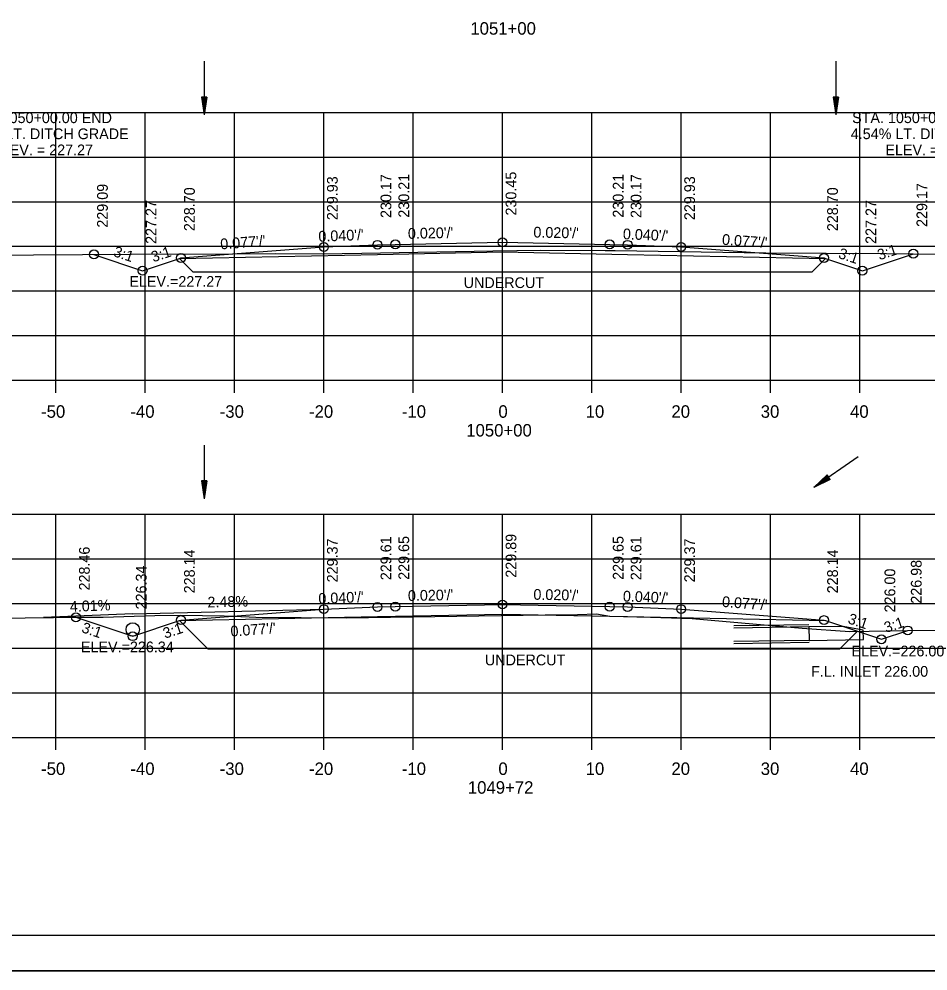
# Model space of a CAD drawing. Extents: x 1386544 to 1388153, y 379785 to 390999.
# Drawn here: x 1387305.6 to 1387407.3, y 387585.5 to 387692.1 of the extents above; entities that cross this region are included whole.
import ezdxf

# ---------------------------------------------------------------- set-up
doc = ezdxf.new("R2010")
doc.units = 0
for name, color, linetype in [('R_Alt Surface', 7, 'Continuous'), ('R_Axis', 7, 'Continuous'), ('R_Axis Annot', 7, 'Continuous'), ('R_Border', 7, 'Continuous'), ('R_Dimension', 7, 'Continuous'), ('R_Drive', 7, 'Continuous'), ('R_Exist Surface', 7, 'Continuous'), ('R_Fin Surface', 7, 'Continuous'), ('R_Grid', 7, 'Continuous'), ('R_No Plot', 7, 'Continuous'), ('R_Water', 7, 'Continuous'), ('R_Water Annot', 7, 'Continuous'), ('R_Xsect Elev', 7, 'Continuous'), ('R_Xsect Slope', 7, 'Continuous')]:
    doc.layers.add(name, color=color, linetype=linetype)

msp = doc.modelspace()

# ---------------------------------------------------------------- linework, layer by layer
at = {"layer": 'R_Alt Surface'}
for points in [[(1387323.51, 387665.33), (1387345.68, 387665.77), (1387359.68, 387666.05), (1387373.68, 387665.77), (1387395.85, 387665.33)], [(1387323.51, 387624.77), (1387345.68, 387625.21), (1387359.68, 387625.49), (1387373.68, 387625.21), (1387395.85, 387624.77)]]:
    msp.add_lwpolyline(points, dxfattribs=at)
at = {"layer": 'R_Axis'}
for p, q in [((1387209.68, 387651.68), (1387509.68, 387651.68)), ((1387309.68, 387650.28), (1387309.68, 387651.68)), ((1387319.68, 387650.28), (1387319.68, 387651.68)), ((1387329.68, 387650.28), (1387329.68, 387651.68)), ((1387339.68, 387650.28), (1387339.68, 387651.68)), ((1387349.68, 387650.28), (1387349.68, 387651.68)), ((1387359.68, 387650.28), (1387359.68, 387651.68)), ((1387369.68, 387650.28), (1387369.68, 387651.68)), ((1387379.68, 387650.28), (1387379.68, 387651.68)), ((1387389.68, 387650.28), (1387389.68, 387651.68)), ((1387399.68, 387650.28), (1387399.68, 387651.68)), ((1387209.68, 387611.68), (1387509.68, 387611.68)), ((1387309.68, 387610.28), (1387309.68, 387611.68)), ((1387319.68, 387610.28), (1387319.68, 387611.68)), ((1387329.68, 387610.28), (1387329.68, 387611.68)), ((1387339.68, 387610.28), (1387339.68, 387611.68)), ((1387349.68, 387610.28), (1387349.68, 387611.68)), ((1387359.68, 387610.28), (1387359.68, 387611.68)), ((1387369.68, 387610.28), (1387369.68, 387611.68)), ((1387379.68, 387610.28), (1387379.68, 387611.68)), ((1387389.68, 387610.28), (1387389.68, 387611.68)), ((1387399.68, 387610.28), (1387399.68, 387611.68))]:
    msp.add_line(p, q, dxfattribs=at)
at = {"layer": 'R_Border'}
msp.add_line((1387517.86, 387589.51), (1387201.68, 387589.51), dxfattribs=at)
at = {"layer": 'R_Dimension'}
for p, q in [((1387323.51, 387665.33), (1387325.02, 387663.81)), ((1387395.85, 387665.33), (1387394.33, 387663.81)), ((1387323.51, 387624.77), (1387326.72, 387621.56)), ((1387399.43, 387623.57), (1387397.41, 387621.56))]:
    msp.add_line(p, q, dxfattribs=at)
for points in [[(1387325.02, 387663.81), (1387394.33, 387663.81)], [(1387397.41, 387621.56), (1387326.72, 387621.56)]]:
    msp.add_lwpolyline(points, dxfattribs=at)
at = {"layer": 'R_Drive'}
for q in [(1387308.29, 387625.12), (1387339.68, 387626.05)]:
    msp.add_line((1387318.28, 387625.52), q, dxfattribs=at)
at = {"layer": 'R_Exist Surface'}
for points in [[(1387301.7, 387665.7), (1387318.11, 387665.79), (1387329.46, 387665.83), (1387334.22, 387665.86), (1387339.51, 387665.83), (1387343.92, 387665.9), (1387358.61, 387666.19), (1387363.96, 387666.26), (1387371.16, 387666.21), (1387372.28, 387666.21), (1387389.15, 387665.95), (1387402.66, 387665.89), (1387414.56, 387665.74)], [(1387292.2, 387624.84), (1387308.57, 387625.13), (1387309.4, 387625.13), (1387310.87, 387625.14), (1387311.88, 387625.14), (1387314.98, 387625.16), (1387320.76, 387625.34), (1387323.66, 387625.37), (1387328.51, 387625.31), (1387331.33, 387625.18), (1387332.06, 387625.16), (1387342.21, 387625.08), (1387364.47, 387625.41), (1387368.07, 387625.45), (1387370.2, 387625.52), (1387371.71, 387625.26), (1387376.25, 387625.15), (1387380.91, 387625), (1387393.24, 387623.93), (1387398.58, 387623.56), (1387405.02, 387623.66), (1387408.74, 387623.7)]]:
    msp.add_lwpolyline(points, dxfattribs=at)
at = {"layer": 'R_Fin Surface'}
for points in [[(1387313.94, 387665.77), (1387319.38, 387663.95), (1387323.51, 387665.33), (1387323.68, 387665.38), (1387339.68, 387666.61), (1387345.68, 387666.85), (1387347.68, 387666.89), (1387359.68, 387667.13), (1387371.68, 387666.89), (1387373.68, 387666.85), (1387379.68, 387666.61), (1387395.68, 387665.38), (1387395.85, 387665.33), (1387399.97, 387663.95), (1387405.68, 387665.85)], [(1387311.92, 387625.14), (1387318.28, 387623.02), (1387323.51, 387624.77), (1387323.68, 387624.82), (1387339.68, 387626.05), (1387345.68, 387626.29), (1387347.68, 387626.33), (1387359.68, 387626.57), (1387371.68, 387626.33), (1387373.68, 387626.29), (1387379.68, 387626.05), (1387395.68, 387624.82), (1387395.85, 387624.77), (1387402.1, 387622.68), (1387405.05, 387623.66)]]:
    msp.add_lwpolyline(points, dxfattribs=at)
at = {"layer": 'R_Grid'}
for p, q in [((1387209.68, 387681.68), (1387509.68, 387681.68)), ((1387309.68, 387651.68), (1387309.68, 387681.68)), ((1387319.68, 387651.68), (1387319.68, 387681.68)), ((1387329.68, 387651.68), (1387329.68, 387681.68)), ((1387339.68, 387651.68), (1387339.68, 387681.68)), ((1387349.68, 387651.68), (1387349.68, 387681.68)), ((1387359.68, 387651.68), (1387359.68, 387681.68)), ((1387369.68, 387651.68), (1387369.68, 387681.68)), ((1387379.68, 387651.68), (1387379.68, 387681.68)), ((1387389.68, 387651.68), (1387389.68, 387681.68)), ((1387399.68, 387651.68), (1387399.68, 387681.68)), ((1387209.68, 387676.68), (1387509.68, 387676.68)), ((1387209.68, 387671.68), (1387509.68, 387671.68)), ((1387209.68, 387666.68), (1387509.68, 387666.68)), ((1387209.68, 387661.68), (1387509.68, 387661.68)), ((1387209.68, 387656.68), (1387509.68, 387656.68)), ((1387209.68, 387651.68), (1387509.68, 387651.68)), ((1387209.68, 387636.68), (1387509.68, 387636.68)), ((1387309.68, 387611.68), (1387309.68, 387636.68)), ((1387319.68, 387611.68), (1387319.68, 387636.68)), ((1387329.68, 387611.68), (1387329.68, 387636.68)), ((1387339.68, 387611.68), (1387339.68, 387636.68)), ((1387349.68, 387611.68), (1387349.68, 387636.68)), ((1387359.68, 387611.68), (1387359.68, 387636.68)), ((1387369.68, 387611.68), (1387369.68, 387636.68)), ((1387379.68, 387611.68), (1387379.68, 387636.68)), ((1387389.68, 387611.68), (1387389.68, 387636.68)), ((1387399.68, 387611.68), (1387399.68, 387636.68)), ((1387209.68, 387631.68), (1387509.68, 387631.68)), ((1387209.68, 387626.68), (1387509.68, 387626.68)), ((1387209.68, 387621.68), (1387509.68, 387621.68)), ((1387209.68, 387616.68), (1387509.68, 387616.68)), ((1387209.68, 387611.68), (1387509.68, 387611.68))]:
    msp.add_line(p, q, dxfattribs=at)
at = {"layer": 'R_No Plot'}
for p, q in [((1387393.97, 387624.3), (1387385.59, 387624.17)), ((1387394, 387622.3), (1387385.59, 387622.17)), ((1387189.28, 387585.54), (1387522.61, 387585.54))]:
    msp.add_line(p, q, dxfattribs=at)
for points in [[(1387189.27, 387798.87), (1387522.61, 387798.87), (1387522.61, 387585.53), (1387189.27, 387585.53)], [(1387435.6, 387794.97), (1387455.22, 387794.97), (1387455.22, 387785.09), (1387471.33, 387785.09), (1387494.53, 387785.09), (1387494.53, 387760.76), (1387517.86, 387760.76), (1387517.86, 387589.51), (1387201.68, 387589.51), (1387201.68, 387794.97)]]:
    msp.add_lwpolyline(points, close=True, dxfattribs=at)
for centre in [(1387339.68, 387666.61), (1387345.68, 387666.85), (1387347.68, 387666.89), (1387359.68, 387667.13), (1387371.68, 387666.89), (1387373.68, 387666.85), (1387379.68, 387666.61), (1387313.94, 387665.77), (1387323.68, 387665.38), (1387395.68, 387665.38), (1387405.68, 387665.85), (1387319.38, 387663.95), (1387399.97, 387663.95), (1387339.68, 387626.05), (1387345.68, 387626.29), (1387347.68, 387626.33), (1387359.68, 387626.57), (1387371.68, 387626.33), (1387373.68, 387626.29), (1387379.68, 387626.05), (1387311.92, 387625.14), (1387323.68, 387624.82), (1387395.68, 387624.82), (1387405.05, 387623.66), (1387318.28, 387623.02), (1387402.1, 387622.68)]:
    msp.add_circle(centre, 0.5, dxfattribs=at)
at = {"layer": 'R_Water'}
for p, q in [((1387326.28, 387687.4), (1387326.28, 387681.4)), ((1387397.01, 387687.4), (1387397.01, 387681.4)), ((1387325.98, 387683.4), (1387326.28, 387681.4)), ((1387326.58, 387683.4), (1387325.98, 387683.4)), ((1387325.98, 387683.4), (1387326.28, 387681.4)), ((1387326.58, 387683.4), (1387325.98, 387683.4)), ((1387326.03, 387683.4), (1387326.28, 387681.73)), ((1387326.03, 387683.4), (1387326.28, 387681.73)), ((1387326.08, 387683.4), (1387326.28, 387682.08)), ((1387326.08, 387683.4), (1387326.28, 387682.08)), ((1387326.13, 387683.4), (1387326.28, 387682.41)), ((1387326.13, 387683.4), (1387326.28, 387682.41)), ((1387326.18, 387683.4), (1387326.28, 387682.75)), ((1387326.18, 387683.4), (1387326.28, 387682.75)), ((1387326.23, 387683.4), (1387326.28, 387683.08)), ((1387326.23, 387683.4), (1387326.28, 387683.08)), ((1387326.58, 387683.4), (1387326.28, 387681.4)), ((1387326.38, 387683.4), (1387326.28, 387682.75)), ((1387326.48, 387683.4), (1387326.28, 387682.08)), ((1387326.53, 387683.4), (1387326.28, 387681.73)), ((1387326.43, 387683.4), (1387326.28, 387682.41)), ((1387326.33, 387683.4), (1387326.28, 387683.08)), ((1387326.58, 387683.4), (1387326.28, 387681.4)), ((1387326.38, 387683.4), (1387326.28, 387682.75)), ((1387326.48, 387683.4), (1387326.28, 387682.08)), ((1387326.53, 387683.4), (1387326.28, 387681.73)), ((1387326.43, 387683.4), (1387326.28, 387682.41)), ((1387326.33, 387683.4), (1387326.28, 387683.08)), ((1387396.71, 387683.4), (1387397.01, 387681.4)), ((1387397.31, 387683.4), (1387396.71, 387683.4)), ((1387396.71, 387683.4), (1387397.01, 387681.4)), ((1387397.31, 387683.4), (1387396.71, 387683.4)), ((1387396.76, 387683.4), (1387397.01, 387681.73)), ((1387396.76, 387683.4), (1387397.01, 387681.73)), ((1387396.81, 387683.4), (1387397.01, 387682.08)), ((1387396.81, 387683.4), (1387397.01, 387682.08)), ((1387396.86, 387683.4), (1387397.01, 387682.41)), ((1387396.86, 387683.4), (1387397.01, 387682.41)), ((1387396.91, 387683.4), (1387397.01, 387682.75)), ((1387396.91, 387683.4), (1387397.01, 387682.75)), ((1387396.96, 387683.4), (1387397.01, 387683.08)), ((1387396.96, 387683.4), (1387397.01, 387683.08)), ((1387397.31, 387683.4), (1387397.01, 387681.4)), ((1387397.11, 387683.4), (1387397.01, 387682.75)), ((1387397.21, 387683.4), (1387397.01, 387682.08)), ((1387397.26, 387683.4), (1387397.01, 387681.73)), ((1387397.16, 387683.4), (1387397.01, 387682.41)), ((1387397.06, 387683.4), (1387397.01, 387683.08)), ((1387397.31, 387683.4), (1387397.01, 387681.4)), ((1387397.11, 387683.4), (1387397.01, 387682.75)), ((1387397.21, 387683.4), (1387397.01, 387682.08)), ((1387397.26, 387683.4), (1387397.01, 387681.73)), ((1387397.16, 387683.4), (1387397.01, 387682.41)), ((1387397.06, 387683.4), (1387397.01, 387683.08)), ((1387326.28, 387644.4), (1387326.28, 387638.4)), ((1387399.48, 387643.11), (1387394.55, 387639.69)), ((1387325.98, 387640.4), (1387326.28, 387638.4)), ((1387326.58, 387640.4), (1387325.98, 387640.4)), ((1387325.98, 387640.4), (1387326.28, 387638.4)), ((1387326.58, 387640.4), (1387325.98, 387640.4)), ((1387326.03, 387640.4), (1387326.28, 387638.73)), ((1387326.03, 387640.4), (1387326.28, 387638.73)), ((1387326.08, 387640.4), (1387326.28, 387639.08)), ((1387326.08, 387640.4), (1387326.28, 387639.08)), ((1387326.13, 387640.4), (1387326.28, 387639.41)), ((1387326.13, 387640.4), (1387326.28, 387639.41)), ((1387326.18, 387640.4), (1387326.28, 387639.75)), ((1387326.18, 387640.4), (1387326.28, 387639.75)), ((1387326.23, 387640.4), (1387326.28, 387640.08)), ((1387326.23, 387640.4), (1387326.28, 387640.08)), ((1387326.58, 387640.4), (1387326.28, 387638.4)), ((1387326.38, 387640.4), (1387326.28, 387639.75)), ((1387326.48, 387640.4), (1387326.28, 387639.08)), ((1387326.53, 387640.4), (1387326.28, 387638.73)), ((1387326.43, 387640.4), (1387326.28, 387639.41)), ((1387326.33, 387640.4), (1387326.28, 387640.08)), ((1387326.58, 387640.4), (1387326.28, 387638.4)), ((1387326.38, 387640.4), (1387326.28, 387639.75)), ((1387326.48, 387640.4), (1387326.28, 387639.08)), ((1387326.53, 387640.4), (1387326.28, 387638.73)), ((1387326.43, 387640.4), (1387326.28, 387639.41)), ((1387326.33, 387640.4), (1387326.28, 387640.08)), ((1387396.02, 387641.08), (1387394.55, 387639.69)), ((1387396.02, 387641.08), (1387394.55, 387639.69)), ((1387396.36, 387640.58), (1387394.55, 387639.69)), ((1387396.36, 387640.58), (1387394.55, 387639.69)), ((1387396.05, 387641.04), (1387394.82, 387639.88)), ((1387396.05, 387641.04), (1387394.82, 387639.88)), ((1387396.33, 387640.63), (1387394.82, 387639.88)), ((1387396.33, 387640.63), (1387394.82, 387639.88)), ((1387396.08, 387640.99), (1387395.1, 387640.08)), ((1387396.08, 387640.99), (1387395.1, 387640.08)), ((1387396.3, 387640.67), (1387395.1, 387640.08)), ((1387396.3, 387640.67), (1387395.1, 387640.08)), ((1387396.1, 387640.95), (1387395.38, 387640.27)), ((1387396.1, 387640.95), (1387395.38, 387640.27)), ((1387396.27, 387640.71), (1387395.38, 387640.27)), ((1387396.27, 387640.71), (1387395.38, 387640.27)), ((1387396.13, 387640.91), (1387395.65, 387640.46)), ((1387396.13, 387640.91), (1387395.65, 387640.46)), ((1387396.24, 387640.75), (1387395.65, 387640.46)), ((1387396.24, 387640.75), (1387395.65, 387640.46)), ((1387396.16, 387640.87), (1387395.93, 387640.65)), ((1387396.16, 387640.87), (1387395.93, 387640.65)), ((1387396.22, 387640.79), (1387395.93, 387640.65)), ((1387396.22, 387640.79), (1387395.93, 387640.65)), ((1387396.36, 387640.58), (1387396.02, 387641.08)), ((1387396.36, 387640.58), (1387396.02, 387641.08)), ((1387393.98, 387624.05), (1387385.59, 387623.92)), ((1387394, 387622.55), (1387385.59, 387622.42))]:
    msp.add_line(p, q, dxfattribs=at)
msp.add_lwpolyline([(1387393.98, 387624.05), (1387394, 387622.55), (1387400.08, 387622.65), (1387400.07, 387623.69), (1387397.81, 387624.11)], close=True, dxfattribs=at)
msp.add_circle((1387318.28, 387623.77), 0.75, dxfattribs=at)

# ---------------------------------------------------------------- texts
at = {"layer": 'R_Axis Annot'}
for s, p in [('1051+00', (1387356.08, 387690.38)), ('-50', (1387308.02, 387647.48)), ('-40', (1387318.02, 387647.48)), ('-30', (1387328.02, 387647.48)), ('-20', (1387338.02, 387647.48)), ('-10', (1387348.41, 387647.48)), ('0', (1387359.22, 387647.48)), ('10', (1387368.99, 387647.48)), ('20', (1387378.59, 387647.48)), ('30', (1387388.59, 387647.48)), ('40', (1387398.59, 387647.48)), ('1050+00', (1387355.62, 387645.38)), ('-50', (1387308.02, 387607.48)), ('-40', (1387318.02, 387607.48)), ('-30', (1387328.02, 387607.48)), ('-20', (1387338.02, 387607.48)), ('-10', (1387348.41, 387607.48)), ('0', (1387359.22, 387607.48)), ('10', (1387368.99, 387607.48)), ('20', (1387378.59, 387607.48)), ('30', (1387388.59, 387607.48)), ('40', (1387398.59, 387607.48)), ('1049+72', (1387355.8, 387605.38))]:
    msp.add_text(s, height=1.4, dxfattribs=at).set_placement(p)
at = {"layer": 'R_Dimension'}
for p in [(1387355.33, 387662.01), (1387357.71, 387619.76)]:
    msp.add_text('UNDERCUT', height=1.2, dxfattribs=at).set_placement(p)
at = {"layer": 'R_Water Annot'}
msp.add_text('F.L. INLET 226.00', height=1.2, dxfattribs=at).set_placement((1387394.22, 387618.48))
at = {"layer": 'R_Xsect Elev'}
for s, p in [('STA. 1050+00.00 END ', (1387299.59, 387680.48)), ('STA. 1050+00.00 BEGIN ', (1387398.82, 387680.48)), ('3.31% LT. DITCH GRADE', (1387299.01, 387678.68)), ('4.54% LT. DITCH GRADE', (1387398.67, 387678.68)), ('ELEV. = 227.27', (1387302.55, 387676.88)), ('ELEV. = 227.27', (1387402.55, 387676.88)), ('ELEV.=227.27', (1387317.9, 387662.15)), ('ELEV.=226.34', (1387312.48, 387621.22)), ('ELEV.=226.00', (1387398.75, 387620.76))]:
    msp.add_text(s, height=1.2, dxfattribs=at).set_placement(p)
for s, rotation, p in [('229.93', 90, (1387341.23, 387669.61)), ('230.17', 90, (1387347.23, 387669.85)), ('230.21', 90, (1387349.23, 387669.89)), ('230.45', 90, (1387361.23, 387670.13)), ('230.21', 90, (1387373.23, 387669.89)), ('230.17', 90, (1387375.23, 387669.85)), ('229.93', 90, (1387381.23, 387669.61)), ('229.09', 90, (1387315.49, 387668.77)), ('228.70', 90, (1387325.23, 387668.38)), ('228.70', 90, (1387397.23, 387668.38)), ('229.17', 90, (1387407.23, 387668.85)), ('227.27', 90, (1387320.93, 387666.95)), ('227.27', 90, (1387401.52, 387666.95)), ('229.37', 90, (1387341.23, 387629.05)), ('229.61', 90, (1387347.23, 387629.29)), ('229.65', 90, (1387349.23, 387629.33)), ('229.89', 90, (1387361.23, 387629.57)), ('229.65', 90, (1387373.23, 387629.33)), ('229.61', 90, (1387375.23, 387629.29)), ('229.37', 90, (1387381.23, 387629.05)), ('228.46', 90, (1387313.47, 387628.14)), ('228.14', 90, (1387325.23, 387627.82)), ('228.14', 90, (1387397.23, 387627.82)), ('226.34', 90, (1387319.83, 387626.02)), ('226.98', 90, (1387406.6, 387626.66)), ('226.00', 90, (1387403.65, 387625.68)), ('2.48%', 1.4191, (1387326.66, 387626.23)), ('4.01%', 2.2981, (1387311.26, 387625.74))]:
    msp.add_text(s, height=1.2, rotation=rotation, dxfattribs=at).set_placement(p)
at = {"layer": 'R_Xsect Slope'}
for s, rotation, p in [("0.077'/'", 4.3987, (1387328.13, 387666.33)), ("0.040'/'", 2.2906, (1387339.09, 387667.19)), ("0.020'/'", 1.1458, (1387349.1, 387667.52)), ("0.020'/'", 358.8542, (1387363.13, 387667.67)), ("0.040'/'", 357.7094, (1387373.14, 387667.48)), ("0.077'/'", 355.6026, (1387384.22, 387666.87)), ('3:1', 18.4349, (1387401.88, 387665.11)), ('3:1', 341.5651, (1387316.03, 387665.6)), ('3:1', 18.4349, (1387320.58, 387664.88)), ('3:1', 341.5651, (1387397.19, 387665.4)), ("0.040'/'", 2.2906, (1387339.09, 387626.63)), ("0.020'/'", 1.1458, (1387349.1, 387626.96)), ("0.020'/'", 358.8542, (1387363.13, 387627.11)), ("0.040'/'", 357.7094, (1387373.14, 387626.92)), ("0.077'/'", 355.6026, (1387384.22, 387626.31)), ('3:1', 341.5651, (1387398.26, 387624.49)), ('3:1', 341.5651, (1387312.47, 387623.49)), ('3:1', 18.4349, (1387321.9, 387622.73)), ("0.077'/'", 4.3987, (1387329.27, 387622.97)), ('3:1', 18.4349, (1387402.63, 387623.38))]:
    msp.add_text(s, height=1.2, rotation=rotation, dxfattribs=at).set_placement(p)

doc.saveas('drawing.dxf')
